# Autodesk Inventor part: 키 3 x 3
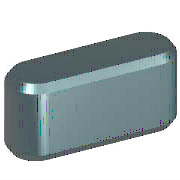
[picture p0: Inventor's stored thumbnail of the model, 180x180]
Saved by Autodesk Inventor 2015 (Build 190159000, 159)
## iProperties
Created: 2012-02
Part Number: 키 3 x 3
Material: 강철, 연강
Description: 키 및 해당 키홈
Document SubType Name: Modeling
Standard: KS B 1311
Designer: mduedu
Standards Organization: KS
Language: ko-KR
Size Designation: 3 x 3 x 12
Categories: <MemberInstance><Categories><Category DisplayName="샤프트 부품" InternalName="7f7aeb1f-a693-4053-b835-cee3144e0d98" Mnemonic="SHFT"><Category DisplayName="키" Interna
Density: 7.86 g/cm^3
Mass: 0.790122 g
Surface Area: 1.42216 cm^2
Volume: 0.100524 cm^3
Appearance: 노란색
IsCustomPart: 1
Author: mduedu
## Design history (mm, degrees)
workplane "Work Plane1"
workplane "Work Plane2"
sketch "스케치1"
  geometry: L1 (1.5, 1.5)-(10.5, 1.5); L2 (10.5, -1.5)-(1.5, -1.5); L3 (0, 9.4)-(0, -7.4) reference; L4 (-5, 0)-(30, 0) reference; L5 (12, 0)-(12, 7); A1 r 1.5 centre (1.5, 0) between (1.5, 1.5) and (1.5, -1.5); A2 r 1.5 centre (10.5, 0) between (10.5, -1.5) and (10.5, 1.5)
  constraints: 6 end point, 5 point on circle, 4 tangent, 3 point on line, 2 centre point, 1 horizontal, 1 parallel, 1 perpendicular
  dimensions: "d0" = 1.5 radius of A1 (= 0.5 x PB); "d13" = 1.5 radius of A2 (= 0.5 x PB); "d14" = 12 distance between parallel lines of L5 L3 (= NLG)
extrude "본체1" new body sketch "스케치1" taper "d3" = 0 deg; stored distance "d4" = 10
workplane "Work Plane3"
body "Solid1"
chamfer "모따기1" distance "d8" = 0.25 (= PHH); stored, may be unused: second distance "d9" = 0.25 (= PHH), angle "d15" = 45 deg
other parameters: "d1" = -1.8 (= -PNT), "d2" = 1.2 (= PH - PNT), "NLG" = 12 [user parameter; used in 3 equation terms], "PB" = 3 [user parameter; used in 2 equation terms], "PNT" = 1.8 [user parameter; used in 2 equation terms], "PH" = 3 [user parameter; used in 1 equation term], "PHH" = 0.25 [user parameter; used in 2 equation terms], "d10" = 0, "d16" = 0, "d17" = 0, "d18" = 0, "WDMIN" = 8 [user parameter], "PLB2" = 12 (= NLG) [user parameter], "PLB1" = 12 (= NLG) [user parameter], "RR" = 0.08 [user parameter], "PUEB" = 1.4 [user parameter]
